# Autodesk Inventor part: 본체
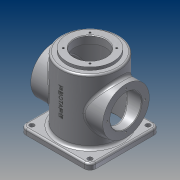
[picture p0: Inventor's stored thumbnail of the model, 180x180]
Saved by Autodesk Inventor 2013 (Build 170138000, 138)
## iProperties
Created: 2015-10
Part Number: 본체
Material: 알루미늄 6061
Document SubType Name: Modeling
Designer: Administrator
Density: 2.71 g/cm^3
Mass: 987.501 g
Surface Area: 1043.35 cm^2
Volume: 364.392 cm^3
Author: Administrator
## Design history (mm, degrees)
sketch "스케치2"
  geometry: L1 (0, 62.5)-(0, -62.5); L2 (27, 62.5)-(40, 62.5); L3 (40, 62.5)-(40, 57.5); L4 (40, 57.5)-(50, 57.5); L5 (50, 57.5)-(50, -62.5); L6 (50, -62.5)-(45, -62.5); L7 (45, -62.5)-(45, 49.5); L8 (45, 49.5)-(27, 49.5); L9 (27, 49.5)-(27, 62.5); L10 (-60, -52.5)-(60, -52.5); L11 (60, -52.5)-(60, -62.5); L12 (60, -62.5)-(-60, -62.5); L13 (-60, -62.5)-(-60, -52.5); 2 further points
  constraints: 26 end point, 8 parallel, 3 perpendicular, 2 midpoint, 1 coincident, 1 horizontal, 1 point on line, 1 vertical
  dimensions: "d2" = 125 distance of L1.end L1.start; "d4" = 54 diameter of L9 L1; "d5" = 80 diameter of L3 L1; "d6" = 100 diameter of L5 L1; "d7" = 13 distance of L8.end L2.start; "d8" = 112 distance of L6.end L7.end; "d9" = 5 distance of L2.end L3.end; "d10" = 90 diameter of L7 L1; "d11" = 120 distance of L11.end L12.end; "d12" = 10 distance between parallel lines of L12 L10
revolve "회전1" stored, may be unused: angle "d13" = 90 deg
extrude "돌출1" join sketch "스케치2" stored distance "d14" = 120; taper "d15" = 0 deg
node "작업 평면1"
sketch "스케치3"
  geometry: C1 r 27 at (0, 0); C2 r 40 at (0, 0); 1 further point
  constraints: 2 centre point, 2 coincident
  dimensions: "d17" = 54 diameter of C1; "d20" = 80 diameter of C2
extrude "돌출2" join sketch "스케치3" stored distance "d21" = 120; taper "d22" = 0 deg
extrude "돌출3" cut sketch "스케치3" stored distance "d23" = 120; taper "d24" = 0 deg
fillet "모깎기1" dims "d25" = 10
sketch "스케치4"
  geometry: L1 (-10, 10)-(-10, 110) reference; L2 (100, 120)-(0, 120) reference; L3 (110, 10)-(110, 110) reference; L4 (0, 0)-(100, 0) reference; A1 r 10 centre (0, 10) between (-10, 10) and (0, 0) reference; A2 r 10 centre (0, 110) between (0, 120) and (-10, 110) reference; A3 r 10 centre (100, 110) between (110, 110) and (100, 120) reference; A4 r 10 centre (100, 10) between (100, 0) and (110, 10) reference; 1 further point
hole "구멍1" sketch "스케치4" at (100, 10), (100, 110), (0, 110), (0, 10) diameter "d26" = 8; stored, may be unused: countersink angle "d30" = 90 deg, drill point angle "d32" = 0 deg; dims "d27" = 6, "d28" = 4, "d29" = 2, "d31" = 8
sketch "스케치5"
  geometry: 2 further points
  constraints: 1 vertical alignment
  dimensions: "d33" = 32.5 distance of point (0, 0) point (0, 32.5)
hole "구멍2" sketch "스케치5" at (0, 32.5) diameter "d34" = 3.242; stored, may be unused: countersink angle "d38" = 90 deg, drill point angle "d40" = 118 deg; dims "d35" = 8, "d36" = 4, "d37" = 2, "d39" = 10
sketch "스케치6"
  geometry: L1 (0, 0)-(22.981, 22.981); L2 (0, 0)-(32.5, 0); 1 further point
  constraints: 4 end point, 1 coincident, 1 equal length, 1 horizontal
  dimensions: "d44" = 32.5 distance of L1.start L1.end; "d45" = 45 deg angle of L2 L1
hole "구멍3" sketch "스케치6" at (22.981, 22.981) diameter "d46" = 3.242; stored, may be unused: countersink angle "d50" = 90 deg, drill point angle "d52" = 118 deg; dims "d47" = 8, "d48" = 4, "d49" = 2, "d51" = 10
fillet "모깎기2" dims "d56" = 5
sketch "스케치7"
  geometry: C1 r 45 at (50, 60) reference; C2 r 45 at (50, 60); 1 further point
  constraints: 1 centre point, 1 coincident, 1 concentric
extrude "돌출4" cut sketch "스케치7" stored distance "d57" = 120; taper "d58" = 0 deg
fillet "모깎기3" dims "d59" = 3
chamfer "모따기1" distance "d60" = 3; stored, may be unused: second distance "d61" = 2, angle "d62" = 45 deg
chamfer "모따기2" distance "d63" = 1; stored, may be unused: second distance "d64" = 2, angle "d65" = 45 deg
node "작업 평면3"
sketch "스케치9"
  geometry: L1 (62.5, 50)-(62.5, -50) reference; 2 further points
  constraints: 1 horizontal alignment, 1 other
  dimensions: "d68" = 70 distance from line of point (-7.5, 0) L1
feature "엠보싱1" sketch "스케치9" dims "d69" = 0.5, "d70" = 0
node "솔리드1"
mirror "대칭1"
pattern_circular "원형 패턴1" dims angle "d42" = 360 deg
mirror "대칭2"
pattern_circular "원형 패턴2" dims angle "d54" = 360 deg
node "투영된 루프1"
other parameters: "d16" = 62
